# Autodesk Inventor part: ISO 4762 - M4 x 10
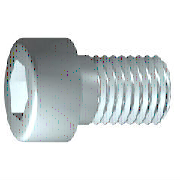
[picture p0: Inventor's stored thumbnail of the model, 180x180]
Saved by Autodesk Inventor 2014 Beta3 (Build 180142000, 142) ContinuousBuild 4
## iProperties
Created: 2010-02
Part Number: ISO 4762 - M4 x 10
Material: Stainless Steel, 440C
Description: Hexagon Socket Head Cap Screw
Document SubType Name: Modeling
Standard: ISO 4762
Designer: Thom Tremblay
Standard Revision: Fourth edition 2004-03-01
Standards Organization: ISO
Language: en-US
Size Designation: M4 x 10
Categories: <MemberInstance><Categories><Category DisplayName="Fasteners" InternalName="e4da775c-781d-43d5-af7c-5136215cf5a6" Mnemonic="FSTN"><Category DisplayName="Bolts"
Density: 7.75 g/cm^3
Appearance: Steel
IsCustomPart: 0
Author: Thom Tremblay
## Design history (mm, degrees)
sketch "Sketch1"
  geometry: L1 (-1, 0)-(10, 0); L2 (10, 0)-(10, 2); L3 (10, 2)-(1.75, 2); L4 (1.75, 2)-(1.32, 2); L5 (1.32, 2)-(0, 2); L6 (0, 2)-(0, 3.5); L7 (0, 3.5)-(-4, 3.5); L8 (-4, 3.5)-(-4, 1.732); L9 (-4, 1.732)-(-2, 1.732); L10 (-2, 1.732)-(-1, 0); L11 (-6.8, 0)-(12.8, 0) reference; L12 (0, -0.7)-(0, 4.2) reference; L13 (1.75, 2)-(0, 2)
  constraints: 22 end point, 6 parallel, 2 collinear, 2 perpendicular, 1 horizontal, 1 point on line
  dimensions: "d1" = 8.25 distance from line of L3.end L2 (= GEL); "d2" = 0.42952 distance of L4.end L3.end (computed from GAL); "d3" = 4 distance between parallel lines of L8 L6 (= KOH); "d4" = 2 distance of L8.end L9.end (= INTI); "d5" = 60 deg angle of L10 L1; "d6" = 4 diameter of L3 L1 (= GD); "d7" = 4 diameter of L5 L1 (= BDM); "d8" = 3.4641 diameter of L9 L1 (= 1.1547 x SW); "d9" = 7 diameter of L7 L1 (= KOD); "d26" = 10 distance between parallel lines of L12 L2 (= NLG)
revolve "Body" sketch "Sketch1" stored, may be unused: angle "d10" = 90 deg
sketch "Sketch2"
  geometry: L1 (0, -4.9)-(0, 4.9) reference; L2 (-4.9, 0)-(4.9, 0) reference; L3 (1.732, 0)-(0.866, -1.5); L4 (0.866, -1.5)-(-0.866, -1.5); L5 (-0.866, -1.5)-(-1.732, 0); L6 (-1.732, 0)-(-0.866, 1.5); L7 (-0.866, 1.5)-(0.866, 1.5); L8 (0.866, 1.5)-(1.732, 0); 2 further points
  constraints: 12 end point, 1 coincident, 1 horizontal alignment, 1 point on line, 12 other
extrude "Slot" join sketch "Sketch2" stored distance "d11" = 10; taper "d12" = 0 deg
workplane "Work Plane1"
fillet "Fillet2" dims "d30" = 0.1 (= R)
body "Solid1"
fillet "Fillet1" dims "d17" = 0.4 (= RR)
feature "Thread" dims "d13" = 8.25 (= GEL), "d14" = 0
chamfer "Chamfer1" distance "d15" = 0.42941 (= -0.5 x SPD + 0.5 x GD); stored, may be unused: second distance "d16" = 0.42941 (= GUL), angle "d27" = 45 deg
other parameters: "GD" = 4 [user parameter; used in 2 equation terms], "NLG" = 10 [user parameter; used in 1 equation term], "GEL" = 8.25 [user parameter; used in 2 equation terms], "KOD" = 7 [user parameter; used in 1 equation term], "KOH" = 4 [user parameter; used in 1 equation term], "INTI" = 2 [user parameter; used in 1 equation term], "GAL" = 0.42941 (= 0.61345 x PTC) [user parameter; used in 1 equation term], "GUL" = 0.42941 (= 0.61345 x PTC) [user parameter; used in 1 equation term], "BDM" = 4 (= NND) [user parameter; used in 1 equation term], "SW" = 3 [user parameter; used in 2 equation terms], "RR" = 0.4 [user parameter; used in 1 equation term], "SPD" = 3.14117 (= NND - 1.2269 x PTC) [user parameter; used in 1 equation term], "d19" = 0, "d28" = 0, "d29" = 0, "R" = 0.1 [user parameter; used in 1 equation term], "TOA" = 30 deg [user parameter], "GD1" = 3.14117 (= THREADDIA - 1.2269 x PTC) [user parameter], "THREADDIA" = 4 [user parameter; used in 1 equation term], "FAWI" = 45 deg [user parameter], "TPU" = 14.28571 (computed from PTC) [user parameter], "PTC" = 0.7 [user parameter; used in 5 equation terms], "NND" = 4 [user parameter; used in 2 equation terms], "E0" = 3.465 (= 1.155 x SW) [user parameter]
